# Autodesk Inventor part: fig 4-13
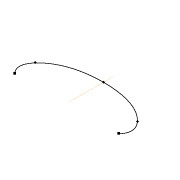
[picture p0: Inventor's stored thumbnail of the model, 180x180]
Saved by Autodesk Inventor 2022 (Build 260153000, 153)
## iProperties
Created: 2012-07
Part Number: fig 4-13
Material: Generic
Document SubType Name: Modeling
Designer: CADCIM
Density: 1 g/cm^3
Appearance: Default
Author: CADCIM
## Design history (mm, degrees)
sketch "Sketch1"
  geometry: L1 (0.121, 13.041)-(0.121, 1.483); L2 (-10.815, -1.576)-(-15.691, 3.573); L3 (-3.522, 10.439)-(3.764, 10.439); L4 (-14.873, 3.848)-(-11.149, 8.074); L5 (11.391, 8.074)-(15.115, 3.848); L6 (15.933, 3.573)-(11.057, -1.576); A1 r 5.401 centre (-9.332, 4.712) between (-14.53, 3.248) and (-11.076, -0.399); A2 r 30.439 centre (0.121, -20) between (3.022, 10.3) and (-2.78, 10.3); A3 r 7.63 centre (-7.286, 0.917) between (-11.348, 7.376) and (-14.205, 4.133); A4 r 7.63 centre (7.528, 0.917) between (14.447, 4.133) and (11.59, 7.376); A5 r 5.401 centre (9.574, 4.712) between (11.318, -0.399) and (14.772, 3.248); 5 further points
  constraints: 12 end point, 10 symmetric about line, 8 midpoint, 5 centre point, 5 point on circle, 1 vertical, 19 other
